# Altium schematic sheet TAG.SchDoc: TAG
size A4; CompanyName: STMicroelectronics; Organization: Microcontrollers Division; DocumentNumber: 9; SheetNumber: 15; SheetTotal: 19
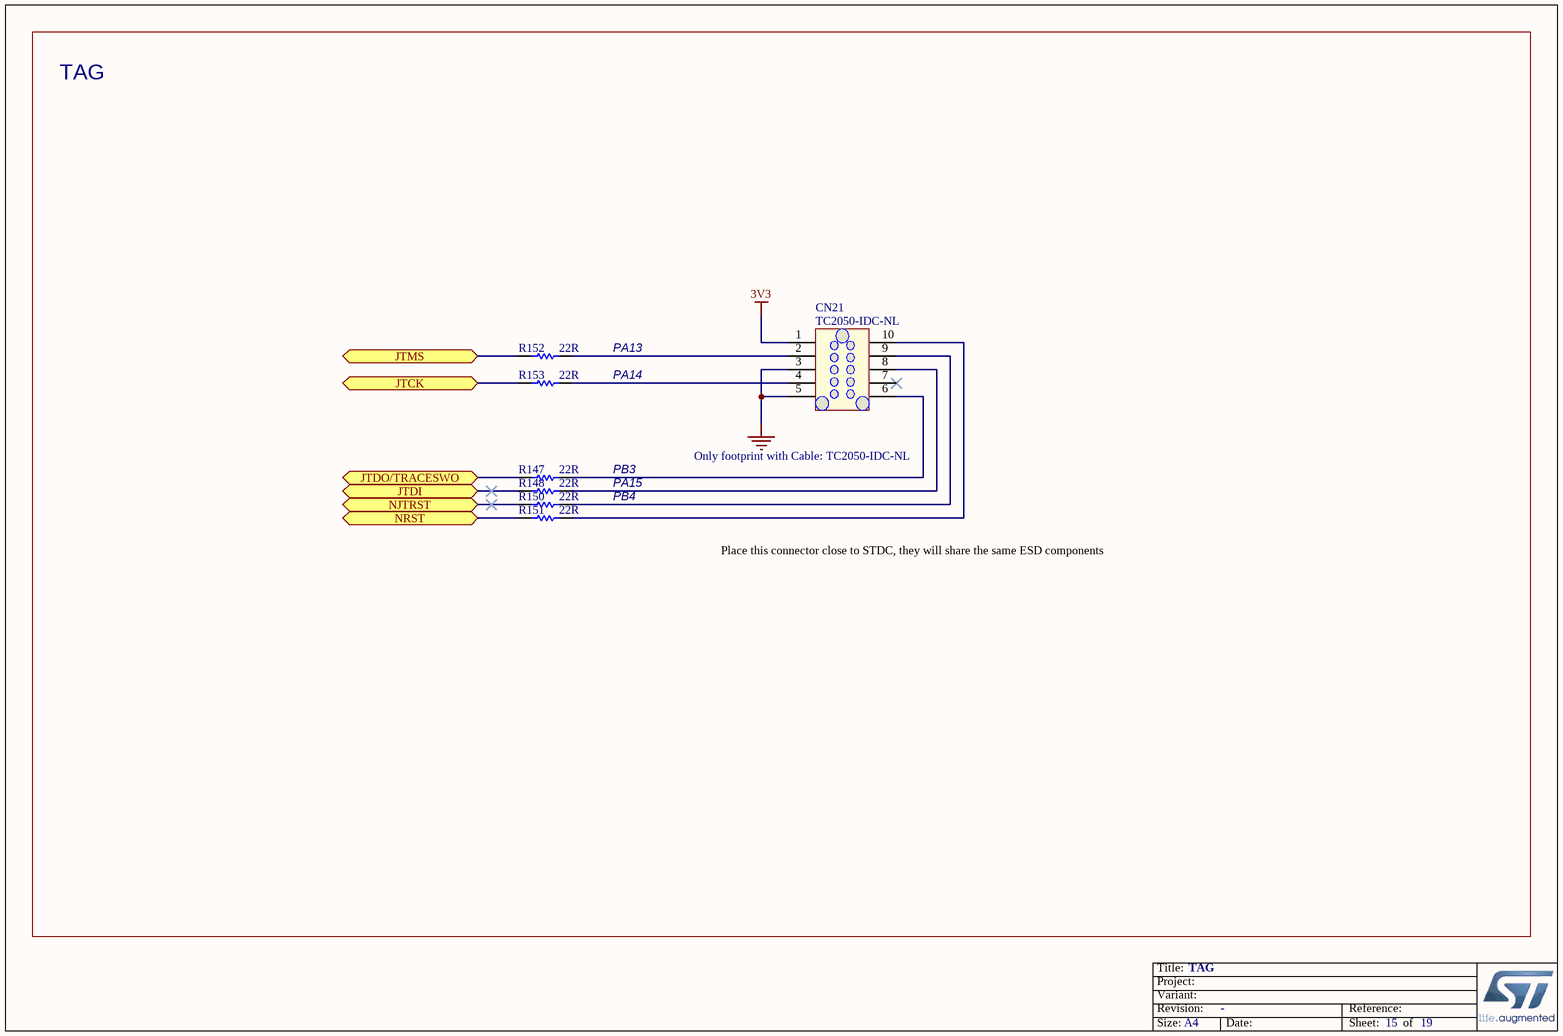
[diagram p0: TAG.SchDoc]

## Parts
CN21  value TC2050-IDC-NL  [CON_TAG-C_TC2050-IDC-NL]  (hidden comment: Tag-10-C)
R147  value 22R  [R0402]  (hidden comment: Resistor)
R148  value 22R  [R0402]  (hidden comment: Resistor)
R150  value 22R  [R0402]  (hidden comment: Resistor)
R151  value 22R  [R0402]  (hidden comment: Resistor)
R152  value 22R  [R0402]  (hidden comment: Resistor)
R153  value 22R  [R0402]  (hidden comment: Resistor)

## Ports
JTCK, JTDI, JTDO/TRACESWO, JTMS, NJTRST, NRST

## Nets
3V3: CN21.1
GND: CN21.3 CN21.5
JTCK: R153.1 ; port JTCK
JTDI: R148.1 ; port JTDI
JTDO/TRACESWO: R147.1 ; port JTDO/TRACESWO
JTMS: R152.1 ; port JTMS
NJTRST: R150.1 ; port NJTRST
NRST: R151.1 ; port NRST
NetCN21_2: CN21.2 R152.2
NetCN21_4: CN21.4 R153.2
NetCN21_6: CN21.6 R147.2
NetCN21_8: CN21.8 R148.2
NetCN21_9: CN21.9 R150.2
NetCN21_10: CN21.10 R151.2

Not connected (* = marked no-connect by the designer): CN21 7*

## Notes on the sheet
- TAG
- PA13
- PA14
- PB3
- PA15
- PB4
- Only footprint with Cable: TC2050-IDC-NL
- Place this connector close to STDC, they will share the same ESD components

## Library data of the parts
CN21 = MCD-00031: Tag_Connector Header, 10x2, No legs; Manufacturer_Part_Number: TC2050-IDC-NL-FP; Manufacturer: TAG-CONNECT LLC; Provided_By: SUBCO
R147 R148 R150-R153 = MCD-00189: Resistor,22R,0402,1%,1/16W; Manufacturer_Part_Number: RC0402FR-0722RL; Manufacturer: YAGEO; Provided_By: SUBCO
